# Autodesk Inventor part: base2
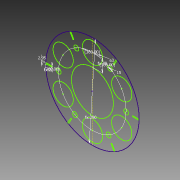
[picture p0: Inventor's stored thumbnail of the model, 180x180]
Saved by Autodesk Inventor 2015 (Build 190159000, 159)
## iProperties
Created: 2017-04
Part Number: base2
Material: Generic
Document SubType Name: Modeling
Designer: mcalderon
Density: 1 g/cm^3
Appearance: Default
Author: mcalderon
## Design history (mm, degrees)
sketch "Sketch1"
  geometry: L1 (124.966, 5.515)-(144.895, 5.515); L2 (144.977, 2.567)-(124.977, 2.567); L3 (124.977, 2.567)-(124.966, 5.515); L4 (57.706, 110.981)-(67.671, 128.241); L5 (70.266, 126.837)-(60.266, 109.517); L6 (60.266, 109.517)-(57.706, 110.981); L7 (-67.259, 105.466)-(-77.224, 122.725); L8 (-74.711, 124.271)-(-64.711, 106.95); L9 (-64.711, 106.95)-(-67.259, 105.466); L10 (-124.966, -5.515)-(-144.895, -5.515); L11 (-144.977, -2.567)-(-124.977, -2.567); L12 (-124.977, -2.567)-(-124.966, -5.515); L13 (-57.706, -110.981)-(-67.671, -128.241); L14 (-70.266, -126.837)-(-60.266, -109.517); L15 (-60.266, -109.517)-(-57.706, -110.981); L16 (67.259, -105.466)-(77.224, -122.725); L17 (74.711, -124.271)-(64.711, -106.95); L18 (64.711, -106.95)-(67.259, -105.466); L19 (0, 145)-(0, -145); L20 (0, 105)-(0, 65); C1 r 31.5 at (0, 105); C2 r 31.5 at (-90.933, 52.5); C3 r 31.5 at (-90.933, -52.5); C4 r 31.5 at (0, -105); C5 r 31.5 at (90.933, -52.5); C6 r 31.5 at (90.933, 52.5); C7 r 7.5 at (-54.529, 89.314); C8 r 7.5 at (-104.613, -2.567); C9 r 7.5 at (-50.084, -91.881); C10 r 7.5 at (54.529, -89.314); C11 r 7.5 at (104.613, 2.567); C12 r 7.5 at (50.084, 91.881); A1 r 145 centre (0, 0) between (145, 0) and (144.895, 5.515); 2 further points
  constraints: 40 end point, 13 centre point, 5 point on circle, 2 coincident, 2 point on line, 1 horizontal, 1 parallel, 1 vertical, 1 vertical alignment, 71 other
  dimensions: "d1" = 290 diameter of A1 (= d0 + 4 x space); "d2" = 20 distance of L2.start L2.end (= 0.5 x space); "d3" = 2.95 distance of L1.end L2.start; "d6" = 360 deg dimension on point (0, 0) L1.start (derived); "d8" = 63 diameter of C1; "d9" = 40 distance of L20.end L20.start (= space); "d12" = 360 deg dimension on point (0, 0) L20.start (derived); "d14" = 15 diameter of C7; "d17" = 360 deg dimension on point (0, 0) C7.centre (derived)
other parameters: "space" = 40 [user parameter; used in 3 equation terms]
